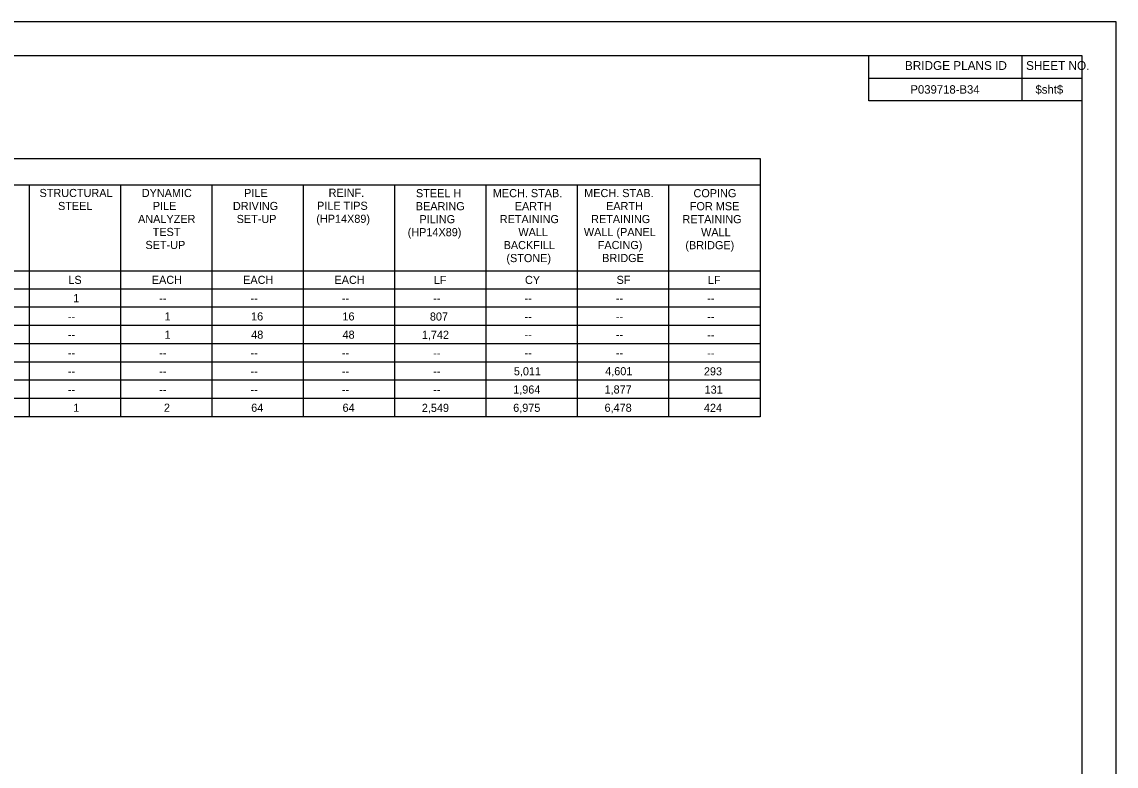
# Model space of a CAD drawing. Extents: x -125.5 to -89.4, y -5.1 to 16.9.
# Drawn here: x -105.71 to -89.53, y 5.93 to 16.93 of the extents above; entities that cross this region are included whole.
import ezdxf

# ---------------------------------------------------------------- set-up
doc = ezdxf.new("R2010")
doc.units = 0
for name, color, linetype in [('BR_BORDER LINES', 7, 'Continuous'), ('BR_TABLE LINES', 7, 'Continuous'), ('BR_TEXT', 7, 'Continuous'), ('Level 31', 7, 'Continuous')]:
    doc.layers.add(name, color=color, linetype=linetype)

msp = doc.modelspace()

# ---------------------------------------------------------------- linework, layer by layer
at = {"layer": 'BR_BORDER LINES'}
for p, q in [((-90.033, 16.434), (-123.699, 16.434)), ((-93.186, 15.767), (-93.186, 16.434)), ((-90.919, 15.767), (-90.919, 16.434)), ((-90.033, -4.566), (-90.033, 16.434)), ((-93.186, 16.104), (-90.033, 16.104)), ((-90.919, 16.104), (-90.033, 16.104)), ((-90.033, 15.767), (-93.186, 15.767))]:
    msp.add_line(p, q, dxfattribs=at)
at = {"layer": 'BR_TABLE LINES'}
for p, q in [((-123.136, 14.914), (-94.796, 14.914)), ((-94.796, 14.913), (-94.796, 11.096)), ((-123.136, 14.524), (-94.796, 14.524)), ((-105.596, 14.524), (-105.596, 11.096)), ((-104.246, 14.524), (-104.246, 11.096)), ((-102.896, 14.524), (-102.896, 11.096)), ((-101.546, 14.524), (-101.546, 11.096)), ((-100.196, 14.521), (-100.196, 11.096)), ((-98.846, 14.523), (-98.846, 11.096)), ((-97.496, 14.523), (-97.496, 11.096)), ((-96.146, 14.522), (-96.146, 11.096)), ((-123.136, 13.256), (-94.796, 13.256)), ((-123.136, 12.986), (-94.796, 12.986)), ((-94.796, 12.716), (-123.136, 12.716)), ((-94.796, 12.446), (-123.136, 12.446)), ((-94.796, 12.176), (-123.136, 12.176)), ((-94.796, 11.906), (-123.136, 11.906)), ((-94.796, 11.636), (-123.136, 11.636)), ((-94.796, 11.366), (-123.136, 11.366)), ((-94.796, 11.096), (-123.136, 11.096))]:
    msp.add_line(p, q, dxfattribs=at)
at = {"layer": 'Level 31'}
msp.add_line((-89.533, 16.934), (-125.533, 16.934), dxfattribs=at)
msp.add_lwpolyline([(-125.533, 16.934), (-125.533, -5.066), (-89.533, -5.066), (-89.533, 16.934)], dxfattribs=at)

# ---------------------------------------------------------------- texts
at = {"layer": 'BR_TEXT'}
for s, height, p in [('BRIDGE PLANS ID', 0.13, (-92.654, 16.224)), ('SHEET NO.', 0.13, (-90.864, 16.224)), ('P039718-B34', 0.125, (-92.573, 15.873)), ('$sht$', 0.125, (-90.724, 15.873)), ('STRUCTURAL ', 0.12, (-105.444, 14.345)), ('DYNAMIC ', 0.12, (-103.933, 14.345)), ('PILE', 0.12, (-102.421, 14.345)), ('REINF. ', 0.12, (-101.172, 14.348)), ('STEEL H ', 0.12, (-99.881, 14.342)), ('MECH. STAB. ', 0.12, (-98.744, 14.343)), ('MECH. STAB. ', 0.12, (-97.394, 14.344)), ('COPING ', 0.12, (-95.779, 14.342)), ('STEEL', 0.12, (-105.171, 14.153)), ('PILE ', 0.12, (-103.769, 14.153)), ('DRIVING', 0.12, (-102.586, 14.153)), ('PILE TIPS ', 0.12, (-101.343, 14.156)), ('BEARING ', 0.12, (-99.883, 14.15)), ('EARTH ', 0.12, (-98.421, 14.151)), ('EARTH ', 0.12, (-97.071, 14.152)), ('FOR MSE ', 0.12, (-95.833, 14.15)), ('ANALYZER ', 0.12, (-103.988, 13.961)), ('SET-UP', 0.12, (-102.531, 13.961)), ('(HP14X89)', 0.12, (-101.354, 13.964)), ('PILING ', 0.12, (-99.829, 13.958)), ('RETAINING ', 0.12, (-98.642, 13.959)), ('RETAINING ', 0.12, (-97.292, 13.96)), ('RETAINING ', 0.12, (-95.942, 13.958)), ('TEST ', 0.12, (-103.772, 13.769)), ('(HP14X89)', 0.12, (-100.003, 13.766)), ('WALL ', 0.12, (-98.367, 13.767)), ('WALL (PANEL ', 0.12, (-97.399, 13.768)), ('WALL ', 0.12, (-95.667, 13.766)), ('SET-UP', 0.12, (-103.879, 13.577)), ('BACKFILL ', 0.12, (-98.585, 13.575)), ('FACING) ', 0.12, (-97.194, 13.576)), ('(BRIDGE)', 0.12, (-95.899, 13.574)), ('(STONE)', 0.12, (-98.544, 13.383)), ('BRIDGE', 0.12, (-97.128, 13.384)), ('LS', 0.12, (-105.018, 13.061)), ('EACH', 0.12, (-103.785, 13.061)), ('EACH', 0.12, (-102.435, 13.061)), ('EACH', 0.12, (-101.085, 13.061)), ('LF', 0.12, (-99.616, 13.059)), ('CY', 0.12, (-98.269, 13.06)), ('SF', 0.12, (-96.916, 13.061)), ('LF', 0.12, (-95.566, 13.059)), ('1', 0.12, (-104.946, 12.791)), ('--', 0.12, (-103.676, 12.791)), ('--', 0.12, (-102.326, 12.791)), ('--', 0.12, (-100.976, 12.791)), ('--', 0.12, (-99.626, 12.789)), ('--', 0.12, (-98.276, 12.79)), ('--', 0.12, (-96.926, 12.791)), ('--', 0.12, (-95.576, 12.789)), ('1', 0.12, (-103.596, 12.521)), ('16', 0.12, (-102.318, 12.521)), ('16', 0.12, (-100.968, 12.521)), ('807', 0.12, (-99.675, 12.519)), ('--', 0.12, (-105.026, 12.521)), ('--', 0.12, (-98.276, 12.52)), ('--', 0.12, (-96.926, 12.521)), ('--', 0.12, (-95.576, 12.519)), ('--', 0.12, (-105.026, 12.251)), ('1', 0.12, (-103.596, 12.251)), ('48', 0.12, (-102.316, 12.251)), ('48', 0.12, (-100.966, 12.251)), ('1,742', 0.12, (-99.794, 12.249)), ('--', 0.12, (-98.276, 12.25)), ('--', 0.12, (-96.926, 12.251)), ('--', 0.12, (-95.576, 12.249)), ('--', 0.12, (-105.026, 11.981)), ('--', 0.12, (-103.676, 11.981)), ('--', 0.12, (-102.326, 11.981)), ('--', 0.12, (-100.976, 11.981)), ('--', 0.12, (-99.626, 11.979)), ('--', 0.12, (-98.276, 11.98)), ('--', 0.12, (-96.926, 11.981)), ('--', 0.12, (-95.576, 11.979)), ('5,011', 0.12, (-98.434, 11.71)), ('4,601', 0.12, (-97.084, 11.711)), ('293', 0.12, (-95.625, 11.709)), ('--', 0.12, (-105.026, 11.711)), ('--', 0.12, (-103.676, 11.711)), ('--', 0.12, (-102.326, 11.711)), ('--', 0.12, (-100.976, 11.711)), ('--', 0.12, (-99.626, 11.709)), ('--', 0.12, (-105.026, 11.441)), ('--', 0.12, (-103.676, 11.441)), ('--', 0.12, (-102.326, 11.441)), ('--', 0.12, (-100.976, 11.441)), ('--', 0.12, (-99.626, 11.439)), ('1,964', 0.12, (-98.444, 11.44)), ('1,877', 0.12, (-97.094, 11.441)), ('131', 0.12, (-95.615, 11.439)), ('1', 0.12, (-104.946, 11.171)), ('2', 0.12, (-103.606, 11.171)), ('64', 0.12, (-102.316, 11.171)), ('64', 0.12, (-100.966, 11.171)), ('2,549', 0.12, (-99.794, 11.169)), ('6,975', 0.12, (-98.444, 11.17)), ('6,478', 0.12, (-97.094, 11.171)), ('424', 0.12, (-95.625, 11.169))]:
    msp.add_text(s, height=height, dxfattribs=at).set_placement(p)

doc.saveas('drawing.dxf')
